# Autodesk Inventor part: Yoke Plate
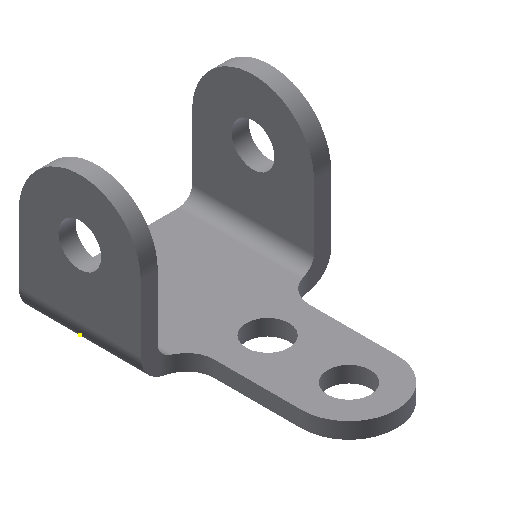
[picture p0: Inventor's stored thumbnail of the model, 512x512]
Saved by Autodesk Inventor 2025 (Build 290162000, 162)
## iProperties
Created: 2011-04
Part Number: Yoke Plate
Material: Generic
Document SubType Name: Modeling
Designer: Dell
Density: 1 g/cm^3
Appearance: Default
Author: Dell
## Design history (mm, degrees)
sketch "Sketch2"
  geometry: L1 (28.5, 36.5)-(28.5, -7.5); L2 (-28.5, -7.5)-(28.5, -7.5); L3 (-28.5, 36.5)-(-28.5, -7.5); C1 r 10 at (0, 36.5); A1 r 28.5 centre (0, 36.5) between (28.5, 36.5) and (-28.5, 36.5); 2 further points
  constraints: 6 end point, 2 centre point, 2 point on circle, 2 tangent, 2 vertical, 1 coincident, 1 perpendicular, 1 other
  dimensions: "d0" = 57 distance of L2.start L1.end; "d1" = 36.5 distance of point (0, 0) C1.centre; "d2" = 28.5 distance from line of L1 point (0, 0); "d3" = 20 diameter of C1; "d24" = 7.5 distance from line of point (0, 0) L2
extrude "Extrusion1" new body sketch "Sketch2" distance "d4" = 89; taper "d5" = 0 deg
sketch "Sketch3"
  geometry: L1 (44, 89)-(0, 89) reference; L2 (-28.588, 8)-(36.5, 8); L3 (36.5, 8)-(36.5, 81); L4 (36.5, 81)-(-28.588, 81); L5 (-28.588, 8)-(-28.588, 81); L6 (-28.5, 89)-(0, 89) reference; 3 further points
  constraints: 8 end point, 1 perpendicular
  dimensions: "d6" = 73 distance of L2.start L4.end; "d9" = 8 distance between parallel lines of L1 L4
extrude "Extrusion2" cut sketch "Sketch3" distance "d10" = 89; taper "d11" = 0 deg
sketch "Sketch4"
  geometry: L1 (0, 58.08)-(53.5, 58.08); L2 (53.5, 13.58)-(0, 13.58); L3 (0, 13.58)-(0, 58.08); L4 (0, 35.83)-(93.365, 35.83); L5 (0, 73)-(0, 0) reference; C1 r 10 at (53.5, 35.83); C2 r 10 at (15.5, 35.83); A1 r 22.25 centre (53.5, 35.83) between (53.5, 13.58) and (53.5, 58.08); 1 further point
  constraints: 8 end point, 3 centre point, 2 horizontal, 2 point on circle, 1 coincident, 1 collinear, 1 equal radius, 1 horizontal alignment, 1 parallel, 1 perpendicular, 1 point on line, 1 tangent
  dimensions: "d12" = 44.5 diameter of A1; "d13" = 44.5 distance between parallel lines of L2 L1; "d14" = 20 diameter of C1; "d15" = 38 distance of A1.centre C2.centre; "d23" = 15.5 distance from line of C2.centre L3
extrude "Extrusion3" join sketch "Sketch4" stored distance "d16" = 89; taper "d17" = 0 deg
fillet "Fillet1" dims "d18" = 12.7
fillet "Fillet2" dims "d19" = 6.35
fillet "Fillet3" dims "d20" = 12.75
body "Solid1"
sketch "Sketch1"
  geometry: 1 further point
